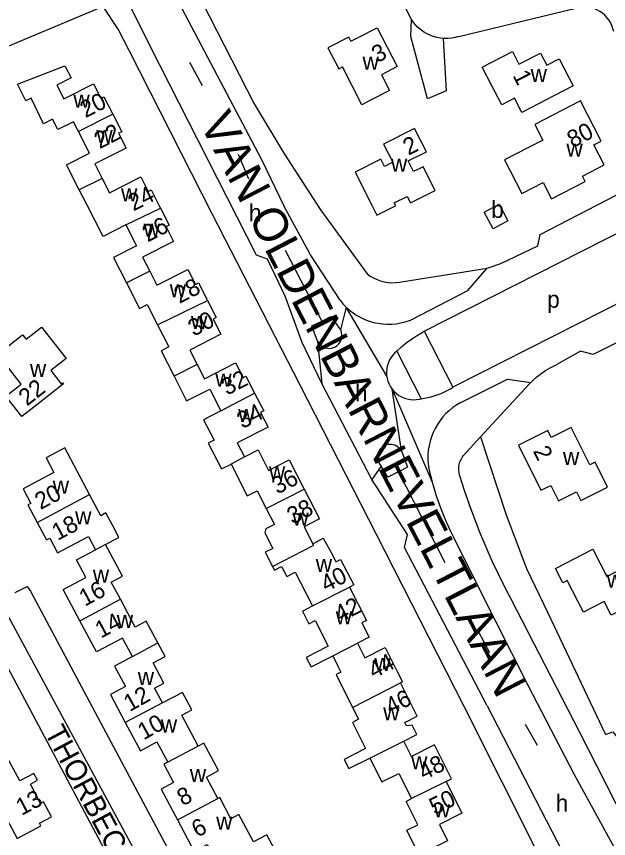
# Model space of a CAD drawing. Extents: x 162427 to 165104, y 384242 to 386287.
# Drawn here: x 163516.1 to 163655.8, y 384850.5 to 385044.6 of the extents above; entities that cross this region are included whole.
import ezdxf

# ---------------------------------------------------------------- set-up
doc = ezdxf.new("R2010")
doc.units = 0
for name, color, linetype in [('BLT_Basislijn', 7, 'Continuous'), ('BLT_Bebouwing', 7, 'Continuous'), ('BLT_Centroide', 7, 'Continuous'), ('BLT_Huisnummer', 7, 'Continuous'), ('BLT_Huisnummer_ tussenligend', 7, 'Continuous'), ('BLT_Onderverdeling_panden', 7, 'Continuous'), ('BLT_Straatnaam', 7, 'Continuous'), ('BLT_Straatnaam_hoofdweg', 7, 'Continuous'), ('BLT_Vlakafsluiter', 7, 'Continuous')]:
    doc.layers.add(name, color=color, linetype=linetype)

msp = doc.modelspace()

# ---------------------------------------------------------------- linework, layer by layer
at = {"layer": 'BLT_Basislijn'}
for p, q in [((163609.31, 385043.84), (163579.69, 385102.22)), ((163536.59, 385046.92), (163365.48, 384975.25)), ((163620.47, 385039.86), (163648.09, 385046.49)), ((163572.76, 384988.26), (163547.61, 385037.74)), ((163562.29, 384997.99), (163542.71, 385036.51)), ((163556.92, 385033.78), (163559.93, 385028.31)), ((163568.41, 385012.1), (163570.86, 385006.26)), ((163612.32, 384970.25), (163670.76, 385000)), ((163583.04, 384957.55), (163562.29, 384997.99)), ((163587.82, 384998.9), (163598.84, 384983.81)), ((163579.48, 384989.37), (163588.13, 384972.68)), ((163677.48, 384986.74), (163619.07, 384957.04)), ((163606.95, 384981.92), (163627.12, 384985.13)), ((163612.32, 384970.25), (163619.07, 384957.04)), ((163605.83, 384965.56), (163611.56, 384954.35)), ((163601.02, 384922.26), (163583.04, 384957.55)), ((163620.9, 384953.42), (163631.91, 384958.97)), ((163625.6, 384945.34), (163637.06, 384957.76)), ((163631.91, 384958.97), (163637.44, 384958.14)), ((163637.06, 384957.76), (163637.44, 384958.14)), ((163621.55, 384940.95), (163625.6, 384945.34)), ((163606.26, 384937.12), (163617.12, 384915.67)), ((163621.68, 384881.66), (163601.02, 384922.26)), ((163619.38, 384921.34), (163625.27, 384909.46)), ((163627.15, 384881.85), (163607.62, 384919.24)), ((163625.27, 384909.46), (163636.73, 384886.74)), ((163632.72, 384907.1), (163648.85, 384875.79)), ((163641.49, 384903.8), (163655.02, 384875.1)), ((163625.04, 384899.47), (163627.68, 384894.47)), ((163636.73, 384886.74), (163647.62, 384865.79)), ((163647.49, 384830.54), (163621.68, 384881.66)), ((163636.11, 384877.51), (163638.94, 384872.6))]:
    msp.add_line(p, q, dxfattribs=at)
for points in [[(163554.47, 385058.67), (163572.18, 385023.98), (163579.15, 385012.29), (163587.82, 384998.9)], [(163549.95, 385056.4), (163573.88, 385010.78), (163579.15, 384999.85)], [(163547.61, 385037.74), (163543.13, 385046.61), (163543.89, 385049.92)], [(163542.71, 385036.51), (163540.11, 385041.61), (163536.59, 385046.92)], [(163656.99, 385041), (163656.82, 385041.73), (163656.57, 385042.43), (163656.25, 385043.11), (163655.86, 385043.75), (163655.4, 385044.34), (163654.88, 385044.88), (163654.31, 385045.36), (163653.69, 385045.78), (163653.03, 385046.13), (163652.33, 385046.41), (163651.61, 385046.61), (163650.87, 385046.74), (163650.12, 385046.78), (163649.38, 385046.74), (163648.64, 385046.63), (163648.09, 385046.49)], [(163616.75, 385039.39), (163617.44, 385026.99), (163613.09, 385025.1), (163609.12, 385039.86), (163609.31, 385043.84)], [(163616.75, 385039.39), (163616.15, 385039.45), (163615.29, 385039.6), (163614.45, 385039.83), (163613.63, 385040.14), (163612.84, 385040.52), (163612.09, 385040.98), (163611.39, 385041.49), (163610.74, 385042.07), (163610.14, 385042.71), (163609.6, 385043.4), (163609.31, 385043.84)], [(163620.47, 385039.86), (163619.63, 385039.62), (163618.77, 385039.46), (163617.9, 385039.37), (163617.02, 385039.37), (163616.75, 385039.39)], [(163627.12, 384985.13), (163630.4, 384986.28), (163639.11, 384990.45), (163639.67, 384993.1), (163662, 385004.65), (163665.41, 385003.7)], [(163592.43, 384977.59), (163585.46, 384988.33), (163579.15, 384999.85)], [(163588.14, 384957.93), (163583.52, 384967.58), (163579.46, 384978.54), (163575.31, 384987.32), (163572.76, 384988.26)], [(163609.02, 384972.88), (163622.59, 384979.85), (163627.12, 384985.13)], [(163598.84, 384983.81), (163599.58, 384983.29), (163600.36, 384982.85), (163601.17, 384982.47), (163602.01, 384982.17), (163602.88, 384981.94), (163603.77, 384981.8), (163604.66, 384981.73), (163605.56, 384981.74), (163606.45, 384981.84), (163606.95, 384981.92)], [(163680.35, 384981.18), (163677.41, 384979.82), (163675.99, 384976.71), (163652.14, 384964.82)], [(163592.43, 384977.59), (163593.12, 384976.76), (163593.86, 384975.98)], [(163593.86, 384975.98), (163594.66, 384975.27), (163595.51, 384974.61), (163596.41, 384974.02), (163597.34, 384973.5), (163598.32, 384973.05), (163599.32, 384972.67), (163600.35, 384972.37), (163601.4, 384972.14), (163602.47, 384972), (163603.54, 384971.93), (163604.61, 384971.95), (163605.68, 384972.04), (163606.74, 384972.22), (163607.79, 384972.47), (163608.81, 384972.8), (163609.02, 384972.88)], [(163588.13, 384972.68), (163590.26, 384973.76), (163592.58, 384970.61)], [(163587.15, 384967.96), (163585.81, 384971.51), (163588.13, 384972.68)], [(163587.15, 384967.96), (163587.4, 384967.53), (163587.71, 384967.15), (163588.08, 384966.83), (163588.49, 384966.57), (163588.95, 384966.38), (163589.43, 384966.26), (163589.92, 384966.23), (163590.4, 384966.28), (163590.88, 384966.4), (163591.33, 384966.6), (163591.74, 384966.87), (163592.1, 384967.2), (163592.4, 384967.59), (163592.64, 384968.02), (163592.8, 384968.48), (163592.89, 384968.97), (163592.9, 384969.46), (163592.82, 384969.94), (163592.67, 384970.41), (163592.58, 384970.61)], [(163605.83, 384965.56), (163606.92, 384966.56), (163608.06, 384967.51), (163609.26, 384968.39), (163610.49, 384969.21), (163611.78, 384969.96), (163612.32, 384970.25)], [(163605.83, 384965.56), (163605.29, 384965.08), (163604.81, 384964.55), (163604.4, 384963.97), (163604.05, 384963.34), (163603.77, 384962.68), (163603.57, 384961.99), (163603.44, 384961.29), (163603.4, 384960.57), (163603.43, 384959.85)], [(163652.14, 384964.82), (163649.17, 384965.58), (163643.61, 384962.44)], [(163637.44, 384958.14), (163637.95, 384958.66), (163638.88, 384959.5), (163639.87, 384960.28), (163640.91, 384960.99), (163641.99, 384961.64), (163643.11, 384962.22), (163643.61, 384962.44)], [(163603.43, 384959.85), (163603.55, 384959.15), (163603.74, 384958.46), (163604.01, 384957.79), (163604.35, 384957.16), (163604.76, 384956.58)], [(163599.93, 384935.28), (163588.14, 384957.93)], [(163604.76, 384956.58), (163605.23, 384956.04), (163605.76, 384955.55), (163606.34, 384955.13), (163606.97, 384954.78), (163607.62, 384954.5), (163608.31, 384954.29), (163609.02, 384954.16), (163609.73, 384954.11), (163610.45, 384954.14), (163611.15, 384954.25), (163611.56, 384954.35)], [(163611.56, 384954.35), (163612.77, 384954.55), (163613.96, 384954.82), (163615.13, 384955.18), (163616.28, 384955.61), (163617.39, 384956.11), (163618.47, 384956.68), (163619.07, 384957.04)], [(163620.9, 384953.42), (163619.96, 384952.87), (163619.07, 384952.25), (163618.23, 384951.57), (163617.43, 384950.83), (163616.7, 384950.03), (163616.02, 384949.18), (163615.41, 384948.28), (163614.87, 384947.34), (163614.4, 384946.37), (163613.99, 384945.36), (163613.67, 384944.32), (163613.43, 384943.26), (163613.26, 384942.19), (163613.17, 384941.11), (163613.16, 384940.02), (163613.23, 384938.94), (163613.38, 384937.86), (163613.61, 384936.8), (163613.92, 384935.77)], [(163625.6, 384945.34), (163631.59, 384926.9), (163636.4, 384914.27), (163641.49, 384903.8)], [(163606.95, 384942.02), (163606.68, 384942.43), (163606.34, 384942.79), (163605.95, 384943.09), (163605.52, 384943.32), (163605.05, 384943.49), (163604.57, 384943.57), (163604.07, 384943.57), (163603.59, 384943.5), (163603.12, 384943.35), (163602.68, 384943.12), (163602.28, 384942.82), (163601.94, 384942.47), (163601.66, 384942.06), (163601.45, 384941.62), (163601.31, 384941.15), (163601.25, 384940.66), (163601.27, 384940.16), (163601.37, 384939.68), (163601.55, 384939.22), (163601.8, 384938.8), (163602.11, 384938.42)], [(163606.95, 384942.02), (163608.32, 384938.16), (163606.26, 384937.12)], [(163620.65, 384936.22), (163620.51, 384936.85), (163620.44, 384937.5), (163620.46, 384938.15), (163620.55, 384938.8), (163620.73, 384939.42), (163620.98, 384940.03), (163621.3, 384940.59), (163621.55, 384940.95)], [(163606.26, 384937.12), (163603.75, 384935.86), (163602.11, 384938.42)], [(163620.65, 384936.22), (163621.73, 384932.79), (163622.89, 384929.39), (163624.13, 384926.02), (163625.44, 384922.67), (163626.82, 384919.35), (163628.28, 384916.07), (163629.81, 384912.82), (163631.41, 384909.6), (163632.72, 384907.1)], [(163607.62, 384919.24), (163608.33, 384922.26), (163599.93, 384935.28)], [(163613.92, 384935.77), (163614.2, 384934.68)], [(163614.2, 384934.68), (163614.49, 384933.59), (163615.14, 384931.44), (163615.86, 384929.31), (163616.67, 384927.21), (163617.54, 384925.14), (163618.49, 384923.1), (163619.38, 384921.34)], [(163499.13, 384918.85), (163551.47, 384820.31), (163567.94, 384789.85)], [(163515.79, 384908.62), (163518.62, 384909.99), (163519.44, 384908.92), (163579.41, 384796.34), (163580.59, 384796.32), (163583.77, 384797.88), (163647.49, 384830.54)], [(163512.07, 384906.8), (163564.56, 384809.44), (163575.38, 384788.87)], [(163627.15, 384881.85), (163651.3, 384835.03), (163653.38, 384834.46), (163654.73, 384831.46)], [(163648.85, 384875.79), (163672.15, 384830.12), (163680.83, 384814.45)], [(163655.02, 384875.1), (163656.82, 384875.74), (163682.02, 384844.18), (163685.23, 384845.12), (163708.81, 384822.49), (163711.21, 384820.11), (163716.64, 384816.24), (163722.73, 384814.86), (163729.83, 384814.83), (163734.58, 384814.89), (163739.86, 384815.36), (163744.65, 384816.02), (163749.74, 384817.26), (163754.17, 384818.73), (163759.07, 384821.05), (163780.9, 384832.02)], [(163647.62, 384865.79), (163670.55, 384823.88), (163675.64, 384813.5), (163678.85, 384806.52), (163681.15, 384801)]]:
    msp.add_lwpolyline(points, dxfattribs=at)
at = {"layer": 'BLT_Bebouwing'}
for p, q in [((163544.09, 384900.46), (163540.62, 384907.02)), ((163583.56, 384904.22), (163585.94, 384905.43))]:
    msp.add_line(p, q, dxfattribs=at)
for points in [[(163595.01, 385038.74), (163596.75, 385039.64), (163601.2, 385041.92), (163605.92, 385032.72), (163602.19, 385030.81), (163604.11, 385027.07), (163599.66, 385024.79), (163597.57, 385023.72), (163592.98, 385032.68)], [(163595.01, 385038.74), (163594.51, 385039.72), (163590.06, 385037.44), (163589.59, 385037.2), (163592.12, 385032.24), (163592.98, 385032.68)], [(163643.02, 385025.9), (163635.32, 385021.91), (163633.57, 385025.28), (163630.57, 385023.72), (163628.26, 385028.18), (163625.96, 385032.61), (163633.09, 385036.31), (163634.64, 385033.31), (163639.7, 385035.93), (163641.19, 385033.06), (163644.15, 385034.6), (163647.46, 385028.2), (163643.02, 385025.9)], [(163530.75, 385017.39), (163529.56, 385019.72), (163525.88, 385017.85), (163524.63, 385020.32), (163522.5, 385019.23), (163519.58, 385025.29), (163518.31, 385024.64), (163516.32, 385028.55), (163527.53, 385032.9), (163528.98, 385030.05), (163525.62, 385028.34), (163527.26, 385025.12), (163534.28, 385028.69), (163536.02, 385025.27), (163536.73, 385025.63), (163538.83, 385021.5)], [(163638.37, 385019.05), (163640.27, 385015.36), (163636.91, 385013.62), (163631.25, 385010.7), (163635.34, 385002.76), (163640.38, 385005.36), (163642.35, 385001.54), (163650.27, 385005.63), (163649.64, 385006.86), (163654.77, 385009.51), (163652.33, 385014.24), (163654.06, 385015.13), (163649.17, 385024.62), (163638.37, 385019.05)], [(163538.83, 385021.5), (163540.93, 385017.36), (163540.2, 385017), (163541.97, 385013.52), (163534.58, 385009.76), (163536.32, 385006.35)], [(163530.94, 385003.61), (163527.93, 385009.53), (163533.34, 385012.29), (163530.75, 385017.39)], [(163605.5, 385000), (163605.22, 385000.55), (163608.27, 385002.11), (163609.07, 385000.55), (163614.89, 385003.52), (163612.03, 385009.11), (163609.8, 385007.97), (163608.52, 385010.47), (163612.8, 385012.65), (163610, 385018.16), (163602.68, 385014.43), (163604.87, 385010.14), (163602.92, 385009.15), (163602.05, 385010.87), (163595.98, 385007.78), (163599.94, 385000), (163601.13, 384997.66), (163605.54, 384999.91), (163605.5, 385000)], [(163536.32, 385006.35), (163538.06, 385002.93), (163545.42, 385006.68), (163547.16, 385003.26), (163547.89, 385003.63), (163549.73, 385000), (163550.09, 384999.31)], [(163541.94, 384995.35), (163536.54, 384992.6), (163532.77, 385000), (163530.94, 385003.61)], [(163550.09, 384999.31), (163552.14, 384995.28), (163551.42, 384994.91), (163553.16, 384991.48), (163545.85, 384987.77), (163547.54, 384984.46)], [(163541.94, 384995.35), (163544.45, 384990.41), (163539.03, 384987.65), (163542.08, 384981.67)], [(163547.54, 384984.46), (163549.23, 384981.14), (163556.52, 384984.88), (163558.33, 384981.34), (163559.05, 384981.71), (163561.19, 384977.53)], [(163542.08, 384981.67), (163545.13, 384975.65), (163546.94, 384976.57), (163549.38, 384971.77)], [(163561.19, 384977.53), (163563.24, 384973.53), (163562.49, 384973.15), (163564.33, 384969.56), (163557.03, 384965.83), (163558.77, 384962.44)], [(163515.03, 384967.43), (163517.57, 384969.42), (163518.37, 384968.4), (163521.99, 384971.25), (163527.84, 384963.8), (163524.19, 384961)], [(163549.38, 384971.77), (163552.02, 384966.58), (163550.21, 384965.66), (163553.28, 384959.63)], [(163524.19, 384961), (163526.69, 384957.82), (163527.05, 384958.1), (163527.23, 384957.87), (163526.87, 384957.59), (163520.88, 384952.87), (163517.38, 384950.12), (163513.6, 384954.93), (163517.23, 384957.78), (163511.7, 384964.81), (163515.03, 384967.43)], [(163558.77, 384962.44), (163560.5, 384959.05), (163567.79, 384962.79), (163569.55, 384959.33), (163570.23, 384959.68), (163572.27, 384955.69)], [(163553.28, 384959.63), (163556.23, 384953.83), (163561.73, 384956.63), (163564.35, 384951.48)], [(163572.27, 384955.69), (163574.43, 384951.47), (163573.69, 384951.09), (163575.47, 384947.62), (163568.2, 384943.9), (163569.89, 384940.6)], [(163564.35, 384951.48), (163560.27, 384949.4), (163562.76, 384944.55), (163561.35, 384943.84), (163564.45, 384937.76), (163566.72, 384938.92)], [(163639.82, 384932.73), (163642.17, 384933.9), (163643.97, 384930.27), (163648.2, 384932.37), (163649.21, 384930.34), (163655.53, 384933.48), (163652.6, 384939.36), (163651.38, 384938.75), (163646.98, 384947.59), (163642.24, 384945.23), (163641.43, 384946.85), (163634.51, 384943.4), (163639.82, 384932.73)], [(163533.36, 384931.72), (163527.5, 384942.74), (163523.08, 384940.4), (163524.93, 384936.93), (163517.68, 384933.08), (163519.5, 384929.65), (163518.81, 384929.28), (163521.01, 384925.15)], [(163569.89, 384940.6), (163573.12, 384942.26), (163575.59, 384937.44), (163580.45, 384939.93), (163583.99, 384933.02)], [(163566.72, 384938.92), (163570.53, 384931.42), (163572.91, 384932.62), (163575.04, 384928.44)], [(163583.99, 384933.02), (163587.6, 384925.98), (163583.99, 384924.13), (163586.04, 384920.11)], [(163538.74, 384924.49), (163537.2, 384927.38), (163536, 384926.74), (163533.36, 384931.72)], [(163575.04, 384928.44), (163576.96, 384924.66), (163574.96, 384923.64), (163574.68, 384922.66), (163576.55, 384918.98), (163574.8, 384918.09), (163576.49, 384914.77)], [(163521.01, 384925.15), (163523.2, 384921.02), (163523.97, 384921.43), (163525.81, 384917.97), (163533.08, 384921.83), (163534.76, 384918.67)], [(163537.14, 384919.93), (163539.17, 384921.01), (163540.27, 384921.6), (163538.74, 384924.49)], [(163586.04, 384920.11), (163588.43, 384921.44), (163590.55, 384917.63), (163591.47, 384915.85), (163592.58, 384916.42), (163595.67, 384910.38), (163594.64, 384909.85)], [(163531.06, 384901.94), (163527.15, 384909.3), (163532.5, 384912.14), (163530.29, 384916.3), (163534.76, 384918.67)], [(163540.62, 384907.02), (163538.46, 384911.08), (163541.09, 384912.48), (163537.14, 384919.93)], [(163659.92, 384900.58), (163658.12, 384904.09), (163656.42, 384903.22), (163654.74, 384906.5), (163649.83, 384903.98), (163646.02, 384911.42), (163644.98, 384910.88), (163643.23, 384914.3), (163652.09, 384918.84), (163655.38, 384912.42), (163660.96, 384915.28), (163666.89, 384903.69), (163664.99, 384902.72)], [(163576.49, 384914.77), (163576.95, 384913.86), (163578.65, 384914.72)], [(163578.65, 384914.72), (163579.86, 384912.36), (163581.89, 384913.39), (163585.94, 384905.43)], [(163594.64, 384909.85), (163598.65, 384902.03), (163597.54, 384901.45), (163599.29, 384898.06), (163596.55, 384896.64)], [(163583.56, 384904.22), (163585.09, 384901.21), (163586.58, 384901.97), (163589.65, 384895.95)], [(163543.48, 384893.48), (163541.09, 384897.84), (163534.97, 384894.58), (163531.06, 384901.94)], [(163549.43, 384896.74), (163546.72, 384901.86), (163544.09, 384900.46)], [(163550.54, 384882.54), (163548.71, 384886.01), (163550.91, 384887.17), (163548.35, 384892.01), (163551.15, 384893.5), (163549.43, 384896.74)], [(163589.65, 384895.95), (163584.47, 384893.3), (163585.63, 384891.03), (163590.71, 384893.62)], [(163596.55, 384896.64), (163598.3, 384893.2), (163603.07, 384895.63), (163605.94, 384889.99), (163607.21, 384887.53), (163606.68, 384887.26)], [(163543.48, 384893.48), (163539.27, 384891.24), (163541.83, 384886.41), (163538.27, 384884.53), (163541.79, 384877.9)], [(163590.71, 384893.62), (163592, 384891.09), (163592.64, 384889.82), (163591.51, 384889.24), (163595.37, 384881.47)], [(163607.73, 384877.93), (163610.67, 384879.42), (163606.68, 384887.26)], [(163558.98, 384872.36), (163555.13, 384879.63), (163557.46, 384880.88), (163555.26, 384885.01), (163550.54, 384882.54)], [(163595.37, 384881.47), (163596.79, 384878.68), (163595.34, 384877.93)], [(163541.79, 384877.9), (163545.34, 384871.21), (163549.24, 384873.39), (163551.8, 384868.57)], [(163595.34, 384877.93), (163598.48, 384871.76), (163593.41, 384869.17), (163594.5, 384867.05), (163599.44, 384869.52)], [(163607.48, 384873.54), (163610.57, 384875.08), (163609.46, 384877.26), (163608.13, 384877.14), (163607.73, 384877.93)], [(163563.61, 384859.95), (163560.9, 384865.05), (163563.77, 384866.57), (163560.32, 384873.08), (163558.98, 384872.36)], [(163617.44, 384864.01), (163618.74, 384864.66), (163614.74, 384872.66), (163609.28, 384869.93), (163607.48, 384873.54)], [(163517.48, 384851.18), (163521.89, 384853.52), (163521.55, 384854.16), (163524.34, 384855.64), (163522.46, 384859.17), (163521.82, 384858.83), (163519.41, 384863.37), (163521.11, 384864.28), (163520.24, 384865.92), (163516.89, 384864.13), (163514.33, 384868.97), (163509.91, 384866.62), (163503.89, 384863.42)], [(163551.8, 384868.57), (163550.88, 384868.09), (163553.18, 384863.75), (163550.23, 384862.19), (163554.1, 384854.91)], [(163599.44, 384869.52), (163602.26, 384863.89), (163606.32, 384865.92), (163609.31, 384859.95)], [(163617.44, 384864.01), (163621.2, 384856.51), (163615.87, 384853.84), (163617.8, 384849.99), (163613.32, 384847.76), (163611.09, 384846.64), (163608.17, 384852.49), (163610.77, 384853.79), (163608.02, 384859.3), (163609.31, 384859.95)], [(163572.02, 384849.74), (163568.6, 384856.19), (163566.71, 384855.19), (163564.06, 384860.19), (163563.61, 384859.95)], [(163512.62, 384857.45), (163516.29, 384850.55), (163517.48, 384851.18)], [(163554.1, 384854.91), (163558.02, 384847.51), (163561.1, 384849.15), (163563.25, 384845.09), (163563.82, 384845.4)], [(163576, 384837.27), (163574.19, 384840.68), (163575.35, 384841.29), (163576.95, 384848.06), (163575.17, 384851.41), (163572.02, 384849.74)]]:
    msp.add_lwpolyline(points, dxfattribs=at)
msp.add_lwpolyline([(163626.46, 384998.41), (163629.96, 385000.26), (163632.04, 384996.33), (163628.54, 384994.48)], close=True, dxfattribs=at)
at = {"layer": 'BLT_Onderverdeling_panden'}
for p, q in [((163538.83, 385021.5), (163530.75, 385017.39)), ((163536.32, 385006.35), (163530.94, 385003.61)), ((163541.94, 384995.35), (163550.09, 384999.31)), ((163547.54, 384984.46), (163542.08, 384981.67)), ((163549.38, 384971.77), (163561.19, 384977.53)), ((163558.77, 384962.44), (163553.28, 384959.63)), ((163564.35, 384951.48), (163572.27, 384955.69)), ((163569.89, 384940.6), (163566.72, 384938.92)), ((163575.04, 384928.44), (163583.99, 384933.02)), ((163521.01, 384925.15), (163533.36, 384931.72)), ((163537.14, 384919.93), (163534.76, 384918.67)), ((163585.94, 384905.43), (163594.64, 384909.85)), ((163531.06, 384901.94), (163540.62, 384907.02)), ((163543.48, 384893.48), (163549.43, 384896.74)), ((163590.71, 384893.62), (163596.55, 384896.64)), ((163595.37, 384881.47), (163606.68, 384887.26)), ((163550.54, 384882.54), (163541.79, 384877.9)), ((163558.98, 384872.36), (163551.8, 384868.57)), ((163599.44, 384869.52), (163607.48, 384873.54)), ((163617.44, 384864.01), (163609.31, 384859.95)), ((163554.1, 384854.91), (163563.61, 384859.95))]:
    msp.add_line(p, q, dxfattribs=at)
msp.add_lwpolyline([(163576.49, 384914.77), (163586.23, 384919.75), (163586.04, 384920.11)], dxfattribs=at)
at = {"layer": 'BLT_Vlakafsluiter'}
for p, q in [((163593.86, 384975.98), (163592.58, 384970.61)), ((163603.43, 384959.85), (163593.86, 384975.98)), ((163587.15, 384967.96), (163588.14, 384957.93)), ((163604.76, 384956.58), (163614.2, 384934.68)), ((163606.95, 384942.02), (163604.76, 384956.58)), ((163602.11, 384938.42), (163599.93, 384935.28))]:
    msp.add_line(p, q, dxfattribs=at)

# ---------------------------------------------------------------- texts
at = {"layer": 'BLT_Centroide'}
for s, p in [('w', (163597.75, 385031.98)), ('w', (163637.39, 385029.09)), ('w', (163529.54, 385023.03)), ('w', (163534.95, 385014.73)), ('w', (163645.84, 385011.47)), ('w', (163604.44, 385007.91)), ('w', (163540.77, 385000.94)), ('h', (163570.94, 384996.25)), ('b', (163628.09, 384997.02)), ('w', (163546.09, 384992.59)), ('w', (163552.27, 384978.31)), ('p', (163641.28, 384975.81)), ('w', (163557.27, 384970.77)), ('w', (163519.28, 384959.5)), ('w', (163563.01, 384957.22)), ('h', (163595.96, 384953.72)), ('w', (163568.41, 384948.86)), ('w', (163645.02, 384938.69)), ('w', (163575.66, 384935.34)), ('w', (163524.66, 384931.94)), ('w', (163529.95, 384924.66)), ('w', (163581.2, 384924.39)), ('w', (163586.71, 384913.44)), ('w', (163534.12, 384910.95)), ('w', (163655.35, 384909.72)), ('w', (163539.77, 384900.25)), ('w', (163591.42, 384901.11)), ('w', (163600.55, 384890.09)), ('w', (163544.72, 384886.8)), ('w', (163602.61, 384878.44)), ('w', (163550.16, 384875.56)), ('w', (163609.2, 384866.88)), ('w', (163557, 384863.88)), ('h', (163643.3, 384856.89)), ('w', (163614.55, 384855.53)), ('w', (163563.21, 384852.66))]:
    msp.add_text(s, height=4, dxfattribs=at).set_placement(p)
at = {"layer": 'BLT_Huisnummer'}
for s, rotation, p in [('3', 27.1442, (163601.19, 385033.52)), ('1', 297.3926, (163633.06, 385030.66)), ('20', 26.9514, (163532.4, 385020.54)), ('80', 27.2837, (163647.3, 385013.47)), ('2', 26.9966, (163608.57, 385011.68)), ('24', 26.9432, (163543.72, 384998.54)), ('28', 27.1184, (163554.58, 384976.73)), ('32', 27.1172, (163565.76, 384955.04)), ('22', 38.2083, (163518.59, 384952.47)), ('2', 296.449, (163637.88, 384942.03)), ('36', 27.1213, (163577.66, 384931.7)), ('20', 27.9877, (163521.79, 384928.06)), ('40', 27.0047, (163589.16, 384908.63)), ('14', 27.985, (163536.01, 384897.7)), ('46', 26.9904, (163604.38, 384879.64)), ('10', 29.1031, (163546.12, 384873.7)), ('48', 26.5607, (163612.21, 384864.22)), ('13', 27.9848, (163517.33, 384855.88)), ('50', 26.5607, (163614.75, 384856.01)), ('6', 27.9527, (163558.76, 384850.69))]:
    msp.add_text(s, height=4, rotation=rotation, dxfattribs=at).set_placement(p)
at = {"layer": 'BLT_Huisnummer_ tussenligend'}
for s, rotation, p in [('22', 26.9514, (163535.73, 385013.23)), ('26', 26.9432, (163547.05, 384991.22)), ('30', 27.1184, (163557.9, 384968.96)), ('34', 27.1172, (163569.41, 384947.16)), ('38', 27.1213, (163581.21, 384924.6)), ('18', 27.985, (163525.82, 384920.77)), ('16', 27.985, (163532.24, 384905.24)), ('42', 27.0047, (163592.39, 384901.43)), ('44', 26.9904, (163600.39, 384888.18)), ('12', 29.1031, (163542.81, 384880.37)), ('8', 27.9527, (163555.33, 384858.12))]:
    msp.add_text(s, height=4, rotation=rotation, dxfattribs=at).set_placement(p)
at = {"layer": 'BLT_Straatnaam'}
msp.add_text('THORBECKELAAN', height=5, rotation=298.1101, dxfattribs=at).set_placement((163522.61, 384875.63))
at = {"layer": 'BLT_Straatnaam_hoofdweg'}
msp.add_text('VAN OLDENBARNEVELTLAAN', height=8, rotation=297.3684, dxfattribs=at).set_placement((163559.17, 385019.45))

doc.saveas('drawing.dxf')
